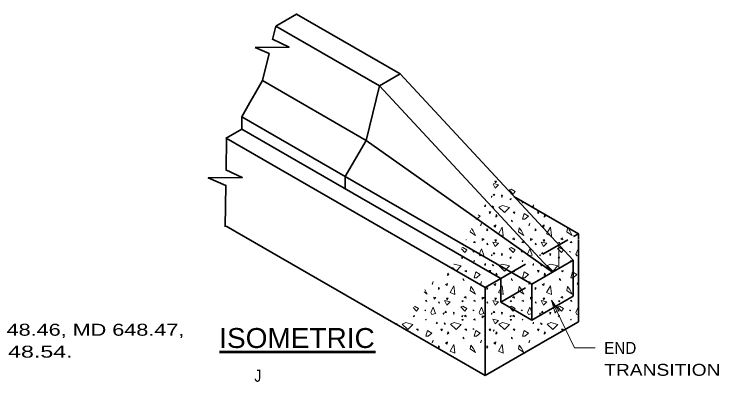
# Model space of a CAD drawing. Extents: x -15.1 to -7.9, y 13.6 to 23.8.
# Drawn here: x -11.564 to -8.029, y 21.913 to 23.76 of the extents above; entities that cross this region are included whole.
import ezdxf
from ezdxf.enums import TextEntityAlignment as Align

# ---------------------------------------------------------------- set-up
doc = ezdxf.new("R2010")
doc.units = 0
doc.header["$LTSCALE"] = 0.024
doc.linetypes.add('LONG_DASHED', pattern=[7.5, 6, -1.5])
for name, color, linetype, lineweight in [('1', 7, 'Continuous', 35), ('10', 7, 'Continuous', 13), ('12', 7, 'Continuous', 53), ('6', 7, 'Continuous', 13)]:
    doc.layers.add(name, color=color, linetype=linetype, lineweight=lineweight)

msp = doc.modelspace()

# ---------------------------------------------------------------- linework, layer by layer
at = {"layer": '1'}
for p, q in [((-10.25167, 23.69967), (-9.732, 23.39967)), ((-10.35133, 23.36717), (-10.3175, 23.42583)), ((-10.3175, 23.42583), (-9.79767, 23.12583)), ((-10.35133, 23.36717), (-10.38117, 23.31533)), ((-10.4225, 23.244), (-10.38117, 23.31533)), ((-10.4225, 23.1825), (-10.4225, 23.244)), ((-8.86333, 22.46383), (-9.79767, 23.12583)), ((-9.90283, 22.8825), (-9.90283, 22.944)), ((-9.05683, 22.84417), (-8.7335, 22.6575)), ((-9.20117, 21.945), (-10.5005, 22.69517)), ((-8.7595, 22.34383), (-8.7595, 22.52383)), ((-9.12317, 22.4325), (-9.20117, 22.3875)), ((-9.12317, 22.31383), (-9.12317, 22.4325)), ((-9.20117, 21.945), (-9.20117, 22.3875)), ((-8.73267, 22.2155), (-8.73267, 22.35767)), ((-8.877, 22.13217), (-8.73267, 22.2155)), ((-9.20117, 21.945), (-8.877, 22.13217))]:
    msp.add_line(p, q, dxfattribs=at)
at = {"layer": '1', "linetype": 'LONG_DASHED'}
for p, q in [((-9.12317, 22.4325), (-8.75817, 22.64317)), ((-9.12317, 22.31383), (-8.97283, 22.40067))]:
    msp.add_line(p, q, dxfattribs=at)
at = {"layer": '1'}
for points in [[(-10.25167, 23.69967), (-10.14783, 23.75967), (-9.628, 23.45967)], [(-9.732, 23.39967), (-9.628, 23.45967), (-8.7595, 22.52383)], [(-10.3175, 23.42583), (-9.79767, 23.12583), (-9.90283, 22.944)], [(-9.79767, 23.12583), (-9.732, 23.39967), (-8.86333, 22.46383)], [(-10.4225, 23.244), (-9.90283, 22.94383), (-8.96733, 22.40367)], [(-9.20117, 22.3875), (-10.5005, 23.1375), (-10.4225, 23.1825), (-9.12317, 22.4325)], [(-8.7335, 22.62883), (-8.7335, 22.6575), (-8.75817, 22.64317)], [(-8.73267, 22.35767), (-8.73267, 22.49117), (-8.73267, 22.62467)], [(-8.96733, 22.22383), (-8.96733, 22.40383), (-8.7595, 22.52383)], [(-8.7595, 22.34383), (-8.96733, 22.22383), (-9.12317, 22.31383)]]:
    msp.add_lwpolyline(points, dxfattribs=at)
at = {"layer": '10', "lineweight": 35}
for p, q in [((-10.2685, 23.63183), (-10.25167, 23.69967)), ((-10.28417, 23.561), (-10.3555, 23.59217)), ((-10.3175, 23.42583), (-10.28467, 23.56233)), ((-10.4985, 23.1375), (-10.50117, 22.97617)), ((-10.50233, 22.9005), (-10.50583, 22.692))]:
    msp.add_line(p, q, dxfattribs=at)
at = {"layer": '10'}
for p, q in [((-8.85033, 22.25833), (-8.86933, 22.32367)), ((-8.83017, 22.268), (-8.86933, 22.32367)), ((-8.85033, 22.25833), (-8.84383, 22.27067)), ((-8.83017, 22.268), (-8.84383, 22.27067))]:
    msp.add_line(p, q, dxfattribs=at)
at = {"layer": '10', "lineweight": 35}
for points in [[(-10.3555, 23.59217), (-10.185, 23.5935), (-10.26817, 23.633)], [(-10.50283, 22.89917), (-10.59, 22.93733), (-10.41967, 22.93867), (-10.50283, 22.97833)]]:
    msp.add_lwpolyline(points, dxfattribs=at)
at = {"layer": '10'}
msp.add_lwpolyline([(-8.64942, 22.084), (-8.754, 22.084), (-8.86933, 22.32367)], dxfattribs=at)
at = {"layer": '12'}
msp.add_line((-10.53392, 22.06517), (-9.75125, 22.06517), dxfattribs=at)
at = {"layer": '6', "linetype": 'LONG_DASHED'}
msp.add_line((-8.83183, 22.47917), (-8.83183, 22.60183), dxfattribs=at)
at = {"layer": '6'}
msp.add_line((-8.86333, 22.46383), (-8.75917, 22.524), dxfattribs=at)
for points in [[(-9.16117, 22.906), (-9.15183, 22.88633), (-9.13383, 22.903), (-9.16, 22.9085)], [(-9.2475, 22.73017), (-9.2445, 22.73017), (-9.226, 22.74567), (-9.23667, 22.75183)], [(-9.275, 22.67367), (-9.27617, 22.66683), (-9.2505, 22.64833), (-9.261, 22.67117), (-9.2705, 22.683)], [(-8.789, 22.68317), (-8.7915, 22.66683), (-8.76583, 22.64833), (-8.77633, 22.67117), (-8.782, 22.67817)], [(-9.29783, 22.62733), (-9.29733, 22.62717), (-9.2975, 22.628)], [(-9.32067, 22.58083), (-9.3035, 22.56233), (-9.29267, 22.57567), (-9.31383, 22.58783), (-9.318, 22.586)], [(-8.73333, 22.57567), (-8.73567, 22.58183), (-8.7475, 22.55483), (-8.7415, 22.5455), (-8.73333, 22.5475)], [(-9.35833, 22.504), (-9.35633, 22.50467), (-9.3215, 22.49567), (-9.34733, 22.46983), (-9.366, 22.48833)], [(-9.508, 22.3655), (-9.49283, 22.35467), (-9.50333, 22.37717)], [(-9.56233, 22.28633), (-9.54583, 22.2685), (-9.535, 22.28183), (-9.555, 22.29333)], [(-8.73267, 22.2805), (-8.73567, 22.288), (-8.7475, 22.261), (-8.7415, 22.25167), (-8.73267, 22.25383)], [(-9.64783, 22.20583), (-9.6455, 22.202), (-9.64267, 22.20333), (-9.64683, 22.20683)], [(-9.16033, 22.16867), (-9.16083, 22.16867), (-9.1565, 22.17483), (-9.155, 22.17183)], [(-8.94767, 22.09133), (-8.95067, 22.09433), (-8.95067, 22.08967)]]:
    msp.add_lwpolyline(points, dxfattribs=at)
for points in [[(-9.15333, 22.921), (-9.149, 22.912), (-9.14433, 22.921)], [(-9.081, 22.87733), (-9.06117, 22.85617), (-9.05033, 22.8695), (-9.07167, 22.88167)], [(-9.17017, 22.84533), (-9.16883, 22.83917), (-9.1655, 22.84533)], [(-9.1565, 22.85617), (-9.15333, 22.85), (-9.16083, 22.85)], [(-9.11883, 22.8515), (-9.117, 22.83917), (-9.114, 22.85)], [(-9.2005, 22.8015), (-9.20483, 22.79383), (-9.2005, 22.79383)], [(-9.07767, 22.83017), (-9.07333, 22.82733), (-9.07167, 22.83483)], [(-9.0125, 22.8165), (-9.01583, 22.81367), (-9.014, 22.8105)], [(-8.95817, 22.8015), (-8.9625, 22.79383), (-8.95817, 22.79383)], [(-9.18067, 22.7665), (-9.17783, 22.7575), (-9.17317, 22.7665)], [(-9.16083, 22.7895), (-9.158, 22.791), (-9.1655, 22.79717)], [(-9.114, 22.7985), (-9.07917, 22.7895), (-9.105, 22.76367), (-9.1325, 22.791)], [(-9.06117, 22.765), (-9.05367, 22.759), (-9.05217, 22.7665)], [(-8.93833, 22.7665), (-8.9355, 22.7575), (-8.93083, 22.7665)], [(-9.14583, 22.75317), (-9.1475, 22.741), (-9.1415, 22.747)], [(-9.00217, 22.73017), (-8.98367, 22.74567), (-9.0065, 22.759), (-9.014, 22.73017)], [(-8.9035, 22.75317), (-8.90517, 22.741), (-8.89917, 22.747)], [(-9.22467, 22.6985), (-9.22317, 22.6985), (-9.22033, 22.71067)], [(-9.158, 22.6955), (-9.149, 22.69083), (-9.1475, 22.70167)], [(-9.07017, 22.72583), (-9.07017, 22.72117), (-9.064, 22.71683)], [(-8.98233, 22.6985), (-8.98083, 22.6985), (-8.978, 22.71067)], [(-8.91567, 22.6955), (-8.90667, 22.69083), (-8.90517, 22.70167)], [(-9.193, 22.68183), (-9.193, 22.67117), (-9.18833, 22.67717)], [(-9.11267, 22.6635), (-9.11117, 22.6455), (-9.13533, 22.656), (-9.1155, 22.6895)], [(-9.03083, 22.68617), (-9.03383, 22.66683), (-9.00817, 22.64833), (-9.01867, 22.67117)], [(-8.95067, 22.68183), (-8.95067, 22.67117), (-8.946, 22.67717)], [(-8.87033, 22.6635), (-8.86883, 22.6455), (-8.893, 22.656), (-8.87317, 22.6895)], [(-9.217, 22.63333), (-9.21567, 22.62283), (-9.20667, 22.63033)], [(-9.15333, 22.62717), (-9.149, 22.61817), (-9.14433, 22.62717)], [(-9.0565, 22.6365), (-9.064, 22.63033), (-9.055, 22.62717)], [(-8.97467, 22.63333), (-8.97333, 22.62283), (-8.96433, 22.63033)], [(-8.911, 22.62717), (-8.90667, 22.61817), (-8.902, 22.62717)], [(-8.81417, 22.6365), (-8.82167, 22.63033), (-8.81267, 22.62717)], [(-9.2595, 22.61383), (-9.252, 22.61067), (-9.2535, 22.61817)], [(-9.193, 22.6045), (-9.18833, 22.60167), (-9.18967, 22.60917)], [(-9.16267, 22.61533), (-9.15183, 22.59267), (-9.13383, 22.60917)], [(-9.07633, 22.61383), (-9.07167, 22.60917), (-9.06867, 22.61383)], [(-9.01717, 22.61383), (-9.00967, 22.61067), (-9.01117, 22.61817)], [(-8.95067, 22.6045), (-8.946, 22.60167), (-8.94733, 22.60917)], [(-8.92033, 22.61533), (-8.9095, 22.59267), (-8.8915, 22.60917)], [(-8.834, 22.61383), (-8.82933, 22.60917), (-8.82633, 22.61383)], [(-8.77483, 22.61383), (-8.76733, 22.61067), (-8.76883, 22.61817)], [(-9.25817, 22.56667), (-9.2625, 22.56817), (-9.25817, 22.56383)], [(-9.226, 22.5455), (-9.208, 22.55017), (-9.22033, 22.58183), (-9.23217, 22.55483)], [(-9.1565, 22.56233), (-9.15333, 22.55617), (-9.16083, 22.55617)], [(-9.11883, 22.55767), (-9.117, 22.5455), (-9.114, 22.55617)], [(-9.081, 22.58367), (-9.06117, 22.56233), (-9.05033, 22.57567), (-9.07167, 22.58783)], [(-9.01583, 22.56667), (-9.02017, 22.56817), (-9.01583, 22.56383)], [(-8.98367, 22.5455), (-8.96567, 22.55017), (-8.978, 22.58183), (-8.98983, 22.55483)], [(-8.91417, 22.56233), (-8.911, 22.55617), (-8.9185, 22.55617)], [(-8.8765, 22.55767), (-8.87467, 22.5455), (-8.87183, 22.55617)], [(-8.83867, 22.58367), (-8.81883, 22.56233), (-8.808, 22.57567), (-8.82933, 22.58783)], [(-8.7735, 22.56667), (-8.77783, 22.56817), (-8.7735, 22.56383)], [(-9.32, 22.5365), (-9.31567, 22.5335), (-9.31383, 22.54117)], [(-9.25483, 22.52267), (-9.25817, 22.51983), (-9.25633, 22.51667)], [(-9.17017, 22.5515), (-9.16883, 22.5455), (-9.1655, 22.5515)], [(-9.07767, 22.5365), (-9.07333, 22.5335), (-9.07167, 22.54117)], [(-9.0125, 22.52267), (-9.01583, 22.51983), (-9.014, 22.51667)], [(-8.928, 22.5515), (-8.9265, 22.5455), (-8.92317, 22.5515)], [(-8.83533, 22.5365), (-8.831, 22.5335), (-8.82933, 22.54117)], [(-8.77017, 22.52267), (-8.7735, 22.51983), (-8.77167, 22.51667)], [(-9.2005, 22.50767), (-9.20483, 22.5), (-9.2005, 22.5)], [(-9.16083, 22.49567), (-9.158, 22.49717), (-9.1655, 22.50333)], [(-9.114, 22.50467), (-9.07917, 22.49567), (-9.105, 22.46983), (-9.1325, 22.49717)], [(-8.95817, 22.50767), (-8.9625, 22.5), (-8.95817, 22.5)], [(-8.9185, 22.49567), (-8.91567, 22.49717), (-8.92317, 22.50333)], [(-8.87183, 22.50467), (-8.83683, 22.49567), (-8.86283, 22.46983), (-8.89017, 22.49717)], [(-9.38817, 22.45933), (-9.38983, 22.44717), (-9.38383, 22.45333)], [(-9.3035, 22.47133), (-9.29583, 22.46517), (-9.2945, 22.47267)], [(-9.2445, 22.43633), (-9.226, 22.45183), (-9.24867, 22.46517), (-9.25633, 22.43633)], [(-9.18067, 22.47267), (-9.17783, 22.46367), (-9.17317, 22.47267)], [(-9.14583, 22.45933), (-9.1475, 22.44717), (-9.1415, 22.45333)], [(-9.06117, 22.47133), (-9.05367, 22.46517), (-9.05217, 22.47267)], [(-9.00217, 22.43633), (-8.98367, 22.45183), (-9.0065, 22.46517), (-9.014, 22.43633)], [(-8.93833, 22.47267), (-8.9355, 22.46367), (-8.93083, 22.47267)], [(-8.9035, 22.45933), (-8.90517, 22.44717), (-8.89917, 22.45333)], [(-8.81883, 22.47133), (-8.81133, 22.46517), (-8.80983, 22.47267)], [(-8.75983, 22.43633), (-8.7415, 22.45183), (-8.76417, 22.46517), (-8.77167, 22.43633)], [(-9.467, 22.40467), (-9.4655, 22.40467), (-9.46267, 22.41683)], [(-9.3125, 22.432), (-9.3125, 22.42733), (-9.30633, 22.423)], [(-9.22467, 22.40467), (-9.22317, 22.40467), (-9.22033, 22.41683)], [(-9.07017, 22.432), (-9.07017, 22.42733), (-9.064, 22.423)], [(-8.98233, 22.40467), (-8.98083, 22.40467), (-8.978, 22.41683)], [(-8.82783, 22.432), (-8.82783, 22.42733), (-8.82167, 22.423)], [(-8.74, 22.40467), (-8.7385, 22.40467), (-8.73567, 22.41683)], [(-9.43533, 22.388), (-9.43533, 22.37733), (-9.4305, 22.38333)], [(-9.40033, 22.40183), (-9.39133, 22.397), (-9.38983, 22.40783)], [(-9.355, 22.36967), (-9.3535, 22.35167), (-9.37767, 22.36217), (-9.35783, 22.39567)], [(-9.27317, 22.39233), (-9.27617, 22.373), (-9.2505, 22.35467), (-9.261, 22.37733)], [(-9.193, 22.388), (-9.193, 22.37733), (-9.18833, 22.38333)], [(-9.158, 22.40183), (-9.149, 22.397), (-9.1475, 22.40783)], [(-9.11267, 22.36967), (-9.11117, 22.35167), (-9.13533, 22.36217), (-9.1155, 22.39567)], [(-9.03083, 22.39233), (-9.03383, 22.373), (-9.00817, 22.35467), (-9.01867, 22.37733)], [(-8.95067, 22.388), (-8.95067, 22.37733), (-8.946, 22.38333)], [(-8.91567, 22.40183), (-8.90667, 22.397), (-8.90517, 22.40783)], [(-8.87033, 22.36967), (-8.86883, 22.35167), (-8.893, 22.36217), (-8.87317, 22.39567)], [(-8.78867, 22.39233), (-8.7915, 22.373), (-8.76583, 22.35467), (-8.77633, 22.37733)], [(-9.29883, 22.34267), (-9.30633, 22.33667), (-9.29733, 22.33333)], [(-9.0565, 22.34267), (-9.064, 22.33667), (-9.055, 22.33333)], [(-8.81417, 22.34267), (-8.82167, 22.33667), (-8.81267, 22.33333)], [(-9.50183, 22.32), (-9.49433, 22.31683), (-9.49567, 22.32433)], [(-9.45933, 22.3395), (-9.458, 22.329), (-9.449, 22.33667)], [(-9.43533, 22.31067), (-9.4305, 22.30783), (-9.432, 22.31533)], [(-9.405, 22.3215), (-9.39417, 22.29883), (-9.37617, 22.31533)], [(-9.39567, 22.33333), (-9.39133, 22.32433), (-9.38667, 22.33333)], [(-9.31867, 22.32), (-9.31383, 22.31533), (-9.311, 22.32)], [(-9.2595, 22.32), (-9.252, 22.31683), (-9.2535, 22.32433)], [(-9.217, 22.3395), (-9.21567, 22.329), (-9.20667, 22.33667)], [(-9.193, 22.31067), (-9.18833, 22.30783), (-9.18967, 22.31533)], [(-9.16267, 22.3215), (-9.15183, 22.29883), (-9.13383, 22.31533)], [(-9.15333, 22.33333), (-9.149, 22.32433), (-9.14433, 22.33333)], [(-9.07633, 22.32), (-9.07167, 22.31533), (-9.06867, 22.32)], [(-9.01717, 22.32), (-9.00967, 22.31683), (-9.01117, 22.32433)], [(-8.97467, 22.3395), (-8.97333, 22.329), (-8.96433, 22.33667)], [(-8.95067, 22.31067), (-8.946, 22.30783), (-8.94733, 22.31533)], [(-8.92033, 22.3215), (-8.9095, 22.29883), (-8.8915, 22.31533)], [(-8.911, 22.33333), (-8.90667, 22.32433), (-8.902, 22.33333)], [(-8.834, 22.32), (-8.82933, 22.31533), (-8.82633, 22.32)], [(-8.77483, 22.32), (-8.76733, 22.31683), (-8.76883, 22.32433)], [(-9.5005, 22.27283), (-9.50467, 22.27433), (-9.5005, 22.27)], [(-9.46833, 22.25167), (-9.45033, 22.25633), (-9.46267, 22.288), (-9.4745, 22.261)], [(-9.32333, 22.28983), (-9.3035, 22.2685), (-9.29267, 22.28183), (-9.31383, 22.29417)], [(-9.25817, 22.27283), (-9.2625, 22.27433), (-9.25817, 22.27)], [(-9.226, 22.25167), (-9.208, 22.25633), (-9.22033, 22.288), (-9.23217, 22.261)], [(-9.081, 22.28983), (-9.06117, 22.2685), (-9.05033, 22.28183), (-9.07167, 22.29417)], [(-9.01583, 22.27283), (-9.02017, 22.27433), (-9.01583, 22.27)], [(-8.98367, 22.25167), (-8.96567, 22.25633), (-8.978, 22.288), (-8.98983, 22.261)], [(-8.83867, 22.28983), (-8.81883, 22.2685), (-8.808, 22.28183), (-8.82933, 22.29417)], [(-8.7735, 22.27283), (-8.77783, 22.27433), (-8.7735, 22.27)], [(-9.56233, 22.24267), (-9.558, 22.23967), (-9.55617, 22.24733)], [(-9.4125, 22.25767), (-9.41117, 22.25167), (-9.40783, 22.25767)], [(-9.39883, 22.2685), (-9.39567, 22.2625), (-9.40317, 22.2625)], [(-9.361, 22.26383), (-9.35933, 22.25167), (-9.35633, 22.2625)], [(-9.32, 22.24267), (-9.31567, 22.23967), (-9.31383, 22.24733)], [(-9.29883, 22.249), (-9.30633, 22.24283), (-9.29733, 22.2395)], [(-9.217, 22.24567), (-9.21567, 22.23533), (-9.20667, 22.24283)], [(-9.17017, 22.25767), (-9.16883, 22.25167), (-9.1655, 22.25767)], [(-9.1565, 22.2685), (-9.15333, 22.2625), (-9.16083, 22.2625)], [(-9.11883, 22.26383), (-9.117, 22.25167), (-9.114, 22.2625)], [(-9.07767, 22.24267), (-9.07333, 22.23967), (-9.07167, 22.24733)], [(-9.0565, 22.249), (-9.064, 22.24283), (-9.055, 22.2395)], [(-8.928, 22.25767), (-8.9265, 22.25167), (-8.92317, 22.25767)], [(-8.91417, 22.2685), (-8.911, 22.2625), (-8.9185, 22.2625)], [(-8.8765, 22.26383), (-8.87467, 22.25167), (-8.87183, 22.2625)], [(-8.83533, 22.24267), (-8.831, 22.23967), (-8.82933, 22.24733)], [(-9.59867, 22.211), (-9.56383, 22.202), (-9.58967, 22.176), (-9.617, 22.20333)], [(-9.49717, 22.229), (-9.5005, 22.226), (-9.49867, 22.22283)], [(-9.44283, 22.21383), (-9.44717, 22.20633), (-9.44283, 22.20633)], [(-9.40317, 22.202), (-9.40033, 22.20333), (-9.40783, 22.2095)], [(-9.35633, 22.211), (-9.3215, 22.202), (-9.34733, 22.176), (-9.37483, 22.20333)], [(-9.31867, 22.22633), (-9.31383, 22.2215), (-9.311, 22.22633)], [(-9.2595, 22.22633), (-9.252, 22.223), (-9.2535, 22.2305)], [(-9.25483, 22.229), (-9.25817, 22.226), (-9.25633, 22.22283)], [(-9.2005, 22.21383), (-9.20483, 22.20633), (-9.2005, 22.20633)], [(-9.16267, 22.22767), (-9.15183, 22.205), (-9.13383, 22.2215)], [(-9.114, 22.211), (-9.07917, 22.202), (-9.105, 22.176), (-9.1325, 22.20333)], [(-9.07633, 22.22633), (-9.07167, 22.2215), (-9.06867, 22.22633)], [(-9.0125, 22.229), (-9.01583, 22.226), (-9.014, 22.22283)], [(-8.95817, 22.21383), (-8.9625, 22.20633), (-8.95817, 22.20633)], [(-8.9185, 22.202), (-8.91567, 22.20333), (-8.92317, 22.2095)], [(-8.87183, 22.211), (-8.83683, 22.202), (-8.86283, 22.176), (-8.89017, 22.20333)], [(-8.77017, 22.229), (-8.7735, 22.226), (-8.77167, 22.22283)], [(-9.54583, 22.1775), (-9.53817, 22.17133), (-9.53683, 22.17883)], [(-9.48667, 22.1425), (-9.46833, 22.158), (-9.491, 22.17133), (-9.49867, 22.1425)], [(-9.423, 22.17883), (-9.42017, 22.16983), (-9.4155, 22.17883)], [(-9.38817, 22.1655), (-9.38983, 22.15333), (-9.38383, 22.1595)], [(-9.3035, 22.1775), (-9.29583, 22.17133), (-9.2945, 22.17883)], [(-9.25817, 22.17917), (-9.2625, 22.1805), (-9.25817, 22.17617)], [(-9.2445, 22.1425), (-9.226, 22.158), (-9.24867, 22.17133), (-9.25633, 22.1425)], [(-9.18067, 22.17883), (-9.17783, 22.16983), (-9.17317, 22.17883)], [(-9.14583, 22.1655), (-9.1475, 22.15333), (-9.1415, 22.1595)], [(-9.06117, 22.1775), (-9.05367, 22.17133), (-9.05217, 22.17883)], [(-9.00217, 22.1425), (-8.98367, 22.158), (-9.0065, 22.17133), (-9.014, 22.1425)], [(-8.93833, 22.17883), (-8.9355, 22.16983), (-8.93083, 22.17883)], [(-8.9035, 22.1655), (-8.90517, 22.15333), (-8.89917, 22.1595)], [(-8.81883, 22.1775), (-8.81133, 22.17133), (-8.80983, 22.17883)], [(-9.3125, 22.13817), (-9.3125, 22.1335), (-9.30633, 22.12917)], [(-9.07017, 22.13817), (-9.07017, 22.1335), (-9.064, 22.12917)], [(-9.467, 22.11083), (-9.4655, 22.11083), (-9.46267, 22.123)], [(-9.43533, 22.09433), (-9.43533, 22.0835), (-9.4305, 22.08967)], [(-9.40033, 22.108), (-9.39133, 22.10333), (-9.38983, 22.114)], [(-9.355, 22.07583), (-9.3535, 22.05783), (-9.37767, 22.06833), (-9.35783, 22.10183)], [(-9.27317, 22.09867), (-9.27617, 22.07917), (-9.2505, 22.06083), (-9.261, 22.0835)], [(-9.22467, 22.11083), (-9.22317, 22.11083), (-9.22033, 22.123)], [(-9.193, 22.09433), (-9.193, 22.0835), (-9.18833, 22.08967)], [(-9.158, 22.108), (-9.149, 22.10333), (-9.1475, 22.114)], [(-9.11267, 22.07583), (-9.11117, 22.05783), (-9.13533, 22.06833), (-9.1155, 22.10183)], [(-9.03083, 22.09867), (-9.03383, 22.07917), (-9.00817, 22.06083), (-9.01867, 22.0835)], [(-8.98233, 22.11083), (-8.98083, 22.11083), (-8.978, 22.123)]]:
    msp.add_lwpolyline(points, close=True, dxfattribs=at)

# ---------------------------------------------------------------- texts
at = {"layer": '12'}
for s, width, p in [('NORMAL BARRIER SEE STDS. MD 648.45, MD 648.46, MD 648.47,', 1.35, (-14.05167, 22.14525)), ('MD 648.48, MD 648.52, MD 648.53, AND MD 648.54.', 1.45, (-14.05167, 22.03525)), ('END', 0.95, (-8.60442, 22.054)), ('TRANSITION', 1.2, (-8.60442, 21.944))]:
    msp.add_text(s, height=0.06001, dxfattribs=dict(at, width=width)).set_placement(p)
for s, height, width, p in [('ISOMETRIC', 0.1, 1.05, (-10.14521, 22.08375)), ('J', 0.06, 0.85, (-10.34158, 21.91425))]:
    msp.add_text(s, height=height, dxfattribs=dict(at, width=width)).set_placement(p, align=Align.CENTER)

doc.saveas('drawing.dxf')
